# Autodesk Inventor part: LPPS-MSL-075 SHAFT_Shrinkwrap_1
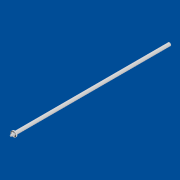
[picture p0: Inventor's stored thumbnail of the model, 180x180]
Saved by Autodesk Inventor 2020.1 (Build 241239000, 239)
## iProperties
Created: 2019-07
Part Number: LPPS-MSL-075 SHAFT_Shrinkwrap_1
Material: Generic
Document SubType Name: Modeling
Designer: J. Nielson
Density: 1 g/cm^3
Appearance: Default
Author: J. Nielson
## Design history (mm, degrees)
node "Assembly1" dims "d0" = 10
body "Solid1"
node "Part1:1" dims "d0" = 10
node "Part2:1" dims "d0" = 10
body "Solid2"
node "Part3:1" dims "d0" = 10
body "Solid3"
